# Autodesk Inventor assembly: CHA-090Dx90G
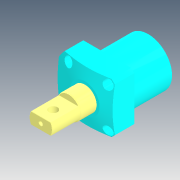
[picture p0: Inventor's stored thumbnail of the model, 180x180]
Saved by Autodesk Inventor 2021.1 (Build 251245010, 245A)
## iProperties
Created: 2018-07
Part Number: CHA-090Dx90G
Description: STEP AP214
Document SubType Name: Assembly
Designer: user
Title: CHA-090Dx90G.STEP
Revision Number: ÈÎºÎ
Sending System: SolidWorks 2016
Preprocessor: SwSTEP 2.0
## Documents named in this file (4)
- D:\Vault_2016\Projekty\Clamptek\Hydraulic\CHA\CHA\CHA-090\Inventor\CHA-090Dx90G\CHA-090Dx90G.iam
- D:\Vault_2016\Projekty\Clamptek\Hydraulic\CHA\CHA\CHA-090\Inventor\CHA-090Dx90G\CHA-090C±¾Ìå.ipt
- D:\Vault_2016\Projekty\Clamptek\Hydraulic\CHA\CHA\CHA-090\Inventor\CHA-090Dx90G\CHA-090D»îÈû¸Ë.ipt
- D:\Vault_2016\Projekty\Clamptek\Hydraulic\CHA\CHA\CHA-090\Inventor\CHA-090Dx90G\G3-8¶ÂÍ·.ipt
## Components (4 placed, 4 different names)
1. CHA-090C±¾Ìå_1
2. CHA-090D»îÈû¸Ë_2
3. G3-8¶ÂÍ·_3
4. G3-8¶ÂÍ·_4
